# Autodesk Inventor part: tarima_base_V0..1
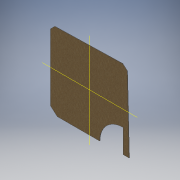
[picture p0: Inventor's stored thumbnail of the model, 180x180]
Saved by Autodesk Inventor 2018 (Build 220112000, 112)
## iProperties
Created: 2018-07
Part Number: tarima_base_V0..1
Material: Generic
Document SubType Name: Modeling
Designer: Gordillo
Density: 1 g/cm^3
Appearance: Default
Author: Gordillo
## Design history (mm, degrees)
sketch "Sketch1"
  geometry: L1 (2800, 0)-(-2800, 0) reference; L2 (0, -2800)-(0, 2800) reference; L3 (2000, 2000)-(-2000, 2000); L4 (-2000, 2000)-(-2000, -2000); L5 (-2000, -2000)-(2000, -2000); L6 (2000, -2000)-(2000, 2000); L7 (-2000, 2000)-(2000, 1900); L8 (-2000, -2000)-(-1900, 2000); L9 (1700, 2000)-(2000, 1700); L10 (2000, -1700)-(1658.606, -2000); L11 (-1650, 2000)-(-2000, 1700); L12 (1794.872, 1905.128)-(2000, 1700); L13 (1794.872, 1905.128)-(-1659.919, 1991.498); L14 (-1659.919, 1991.498)-(-1905.474, 1781.022); L15 (-1905.474, 1781.022)-(-2000, -2000); L16 (-2000, -2000)-(1658.606, -2000); L17 (1658.606, -2000)-(2000, -1700); L18 (2000, 1700)-(2000, -1700); L19 (-2000, -2000)-(-1700, -2000); L20 (-1700, -2000)-(-500, -2000); L21 (-1700, -2000)-(-1700, -800); A1 r 1200 centre (-1700, -2000) between (-500, -2000) and (-1700, -800); 1 further point
  constraints: 38 end point, 16 point on line, 5 collinear, 2 parallel, 2 point on circle, 1 centre point, 1 horizontal, 1 perpendicular, 1 vertical, 2 other
  dimensions: "largo_controlroom" = 4000 distance of L5.end L4.end; "ancho_controlroom" = 4000 distance of L4.end L3.end; "d2" = 100 distance of L3.start L7.end; "d3" = 100 distance of L3.end L8.end; "d4" = 300 distance of L3.start L9.end; "d5" = 300 distance of L3.start L9.start; "d6" = 341.39395 distance of L5.end L10.end; "d7" = 300 distance of L5.end L10.start; "d8" = 300 distance of L3.end L11.end; "d9" = 350 distance of L3.end L11.start; "d12" = 1200 distance of L19.end L20.end; "d13" = 1200 distance of L19.end L21.end; "d14" = 1200 radius of A1; "d15" = 300 distance between parallel lines of L4 L21
extrude "Extrusion2" new body sketch "Sketch1" distance "d16" = 20; taper "d17" = 0 deg
node "TarimaBase"
